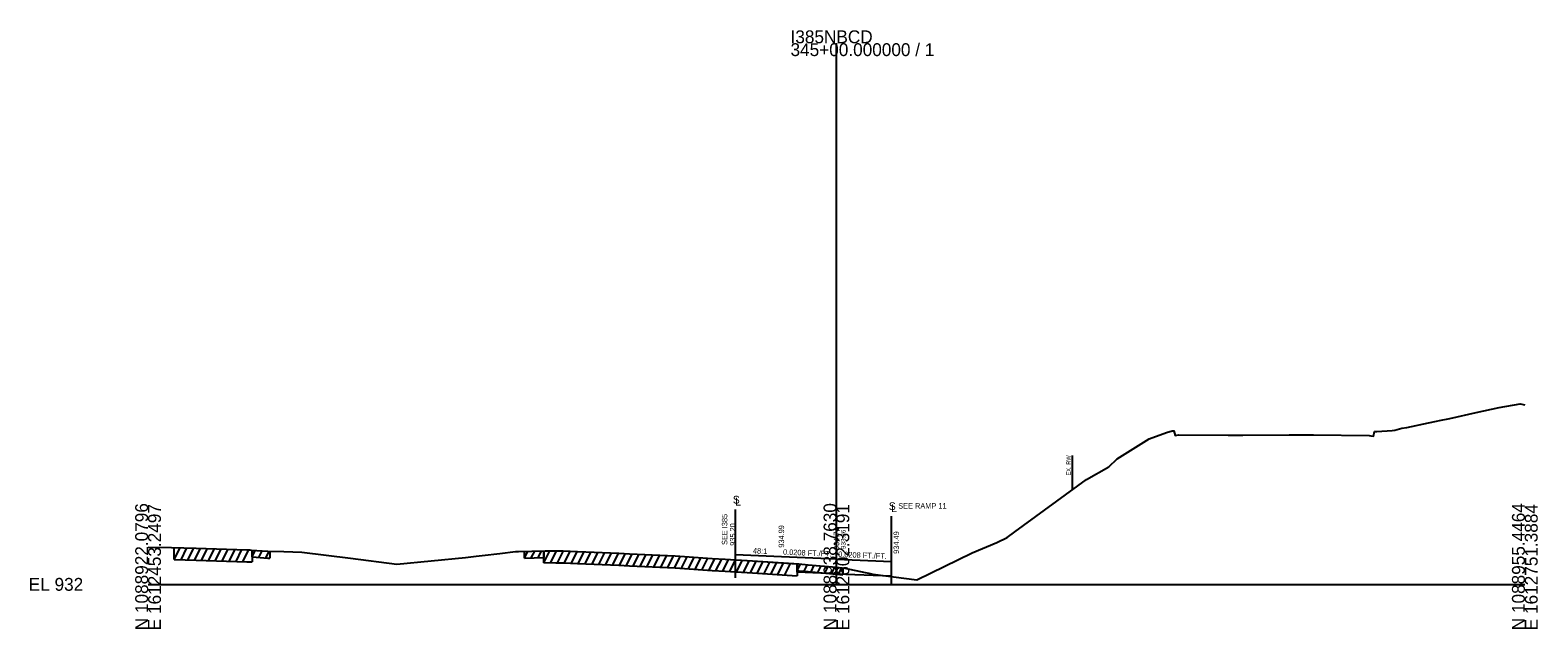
# Model space of a CAD drawing. Extents: x -26 to 1613369, y -10 to 1281970.
# Drawn here: x -25.7 to 302.8, y 15990.3 to 16120.7 of the extents above; entities that cross this region are included whole.
import ezdxf

# ---------------------------------------------------------------- set-up
doc = ezdxf.new("R2010")
doc.units = 0
for name, color, linetype in [('RD_EX_Misc', 7, 'Continuous'), ('RD_GPK_XS_Cell', 7, 'Continuous'), ('RD_Sketch1', 7, 'Continuous'), ('RD_XS_Base', 7, 'Continuous'), ('RD_XS_ExGround', 7, 'Continuous'), ('RD_XS_ExPaveRet', 7, 'Continuous'), ('RD_XS_ExRW', 7, 'Continuous'), ('RD_XS_MatchLine', 7, 'Continuous'), ('RD_XS_Pave', 7, 'Continuous'), ('RD_XS_PaveShd', 7, 'Continuous'), ('RD_XS_TX_Elev_EX', 7, 'Continuous'), ('RD_XS_TX_Elev_PR', 7, 'Continuous'), ('RD_XS_TX_MatchLine', 7, 'Continuous'), ('RD_XS_TX_Notes', 7, 'Continuous'), ('RD_XS_TX_ShdSlope', 7, 'Continuous'), ('RD_XS_TX_Slope', 7, 'Continuous')]:
    doc.layers.add(name, color=color, linetype=linetype)

msp = doc.modelspace()

# ---------------------------------------------------------------- linework, layer by layer
at = {"layer": 'RD_EX_Misc'}
for p, q in [((22.67, 16005.97), (22.67, 16007.47)), ((26.5, 16007.19), (26.5, 16005.69)), ((82, 16005.69), (82, 16007.19)), ((86.24, 16007.32), (86.24, 16005.82)), ((22.67, 16005.97), (26.08, 16005.7)), ((26.08, 16005.7), (26.5, 16005.69)), ((82, 16005.69), (86.24, 16005.82)), ((141.46, 16002.98), (141.46, 16004.48)), ((141.46, 16002.98), (141.83, 16002.96)), ((141.83, 16002.96), (143.83, 16002.78)), ((151.37, 16003.6), (151.37, 16002.1)), ((143.83, 16002.78), (150, 16002.22)), ((150, 16002.22), (151.37, 16002.1))]:
    msp.add_line(p, q, dxfattribs=at)
at = {"layer": 'RD_GPK_XS_Cell'}
for p, q in [((150, 16000), (150, 16117.87)), ((0, 16000), (150, 16000)), ((150, 16000), (300, 16000))]:
    msp.add_line(p, q, dxfattribs=at)
at = {"layer": 'RD_Sketch1'}
for p, q in [((22.67, 16005.97), (23.39, 16007.41)), ((24.17, 16005.85), (24.89, 16007.29)), ((25.67, 16005.73), (26.4, 16007.19)), ((82, 16005.69), (82.76, 16007.21)), ((83.5, 16005.74), (84.26, 16007.26)), ((85, 16005.78), (85.76, 16007.31)), ((141.46, 16002.98), (142.19, 16004.43)), ((142.96, 16002.86), (143.68, 16004.29)), ((144.46, 16002.72), (145.18, 16004.16)), ((145.96, 16002.59), (146.68, 16004.02)), ((147.46, 16002.45), (148.18, 16003.89)), ((148.96, 16002.32), (149.68, 16003.75)), ((150.46, 16002.18), (151.18, 16003.61))]:
    msp.add_line(p, q, dxfattribs=at)
at = {"layer": 'RD_XS_Base'}
for p, q in [((128, 16005.32), (131.74, 16005.09)), ((131.74, 16005.09), (138, 16004.7)), ((138, 16004.7), (141.46, 16004.48)), ((141.46, 16002.67), (141.46, 16004.48)), ((150, 16002.32), (141.46, 16002.67)), ((150, 16002.32), (162, 16001.82))]:
    msp.add_line(p, q, dxfattribs=at)
at = {"layer": 'RD_XS_ExGround'}
msp.add_lwpolyline([(0, 16008.13), (5.1, 16008.01), (10.49, 16007.9), (21.55, 16007.53), (22.14, 16007.51), (22.5, 16007.48), (26.08, 16007.2), (29.56, 16007.12), (33.53, 16006.98), (44.11, 16005.69), (54.2, 16004.41), (69.14, 16005.88), (71.52, 16006.11), (72.81, 16006.27), (76.65, 16006.72), (80.06, 16007.14), (80.69, 16007.15), (86.54, 16007.33), (88.89, 16007.32), (90.44, 16007.31), (93.61, 16007.16), (102.61, 16006.76), (104.9, 16006.65), (114.84, 16006.21), (122.93, 16005.65), (125.74, 16005.46), (131.74, 16005.09), (141.83, 16004.46), (143.83, 16004.28), (150, 16003.72), (151.84, 16003.55), (156.23, 16002.57), (157.05, 16002.41), (157.93, 16002.25), (167.52, 16000.96), (179.6, 16006.86), (184.92, 16009.11), (187.21, 16010.23), (188.88, 16011.47), (204.5, 16022.85), (209.35, 16025.61), (211.15, 16027.33), (218.18, 16031.69), (221.89, 16033.04), (223.14, 16033.43), (223.55, 16033.43), (223.8, 16032.44), (224.56, 16032.54), (235.39, 16032.52), (236.33, 16032.49), (238.59, 16032.5), (248.68, 16032.58), (253.96, 16032.55), (266.11, 16032.4), (266.48, 16032.36), (267.03, 16032.3), (267.28, 16033.3), (267.78, 16033.3), (271.12, 16033.54), (271.69, 16033.57), (272.66, 16033.86), (273.22, 16034), (274.3, 16034.13), (279.04, 16035.2), (280.73, 16035.57), (281.43, 16035.72), (283.67, 16036.13), (289.37, 16037.44), (294.44, 16038.52), (298.96, 16039.29), (300, 16039.12)], dxfattribs=at)
at = {"layer": 'RD_XS_ExPaveRet'}
for p, q in [((5.68, 16005.4), (5.68, 16008)), ((5.68, 16005.4), (6.97, 16007.98)), ((7.18, 16005.37), (8.47, 16007.94)), ((8.68, 16005.34), (9.97, 16007.91)), ((10.18, 16005.31), (11.46, 16007.87)), ((11.68, 16005.26), (12.96, 16007.82)), ((13.18, 16005.21), (14.46, 16007.77)), ((14.68, 16005.16), (15.96, 16007.72)), ((16.18, 16005.11), (17.46, 16007.66)), ((17.68, 16005.06), (18.96, 16007.61)), ((19.18, 16005.01), (20.46, 16007.56)), ((20.68, 16004.96), (21.96, 16007.51)), ((22.67, 16007.47), (22.67, 16004.87)), ((86.24, 16004.72), (87.54, 16007.33)), ((86.24, 16004.72), (86.24, 16007.32)), ((87.74, 16004.73), (89.03, 16007.32)), ((89.24, 16004.72), (90.53, 16007.3)), ((90.74, 16004.69), (92.01, 16007.23)), ((92.24, 16004.62), (93.51, 16007.16)), ((93.74, 16004.55), (95.01, 16007.1)), ((95.24, 16004.49), (96.51, 16007.03)), ((96.74, 16004.42), (98.01, 16006.96)), ((98.24, 16004.35), (99.51, 16006.9)), ((99.74, 16004.29), (101.01, 16006.83)), ((101.24, 16004.22), (102.51, 16006.76)), ((102.74, 16004.15), (104.01, 16006.69)), ((104.24, 16004.08), (105.51, 16006.62)), ((105.74, 16004.01), (107.01, 16006.56)), ((107.24, 16003.95), (108.51, 16006.49)), ((108.74, 16003.88), (110.01, 16006.42)), ((110.24, 16003.81), (111.51, 16006.36)), ((111.74, 16003.74), (113.01, 16006.29)), ((113.24, 16003.68), (114.51, 16006.22)), ((114.74, 16003.61), (116, 16006.13)), ((5.68, 16005.4), (10.49, 16005.3)), ((10.49, 16005.3), (21.55, 16004.93)), ((21.55, 16004.93), (22.14, 16004.91)), ((22.14, 16004.91), (22.5, 16004.88)), ((22.5, 16004.88), (22.67, 16004.87)), ((86.24, 16004.72), (86.54, 16004.73)), ((86.54, 16004.73), (88.89, 16004.72)), ((88.89, 16004.72), (90.44, 16004.71)), ((90.44, 16004.71), (93.61, 16004.56)), ((93.61, 16004.56), (102.61, 16004.16)), ((102.61, 16004.16), (104.9, 16004.05)), ((104.9, 16004.05), (114.84, 16003.61)), ((114.84, 16003.61), (122.93, 16003.05)), ((116.24, 16003.51), (117.5, 16006.02)), ((117.74, 16003.41), (119, 16005.92)), ((119.24, 16003.31), (120.5, 16005.82)), ((120.74, 16003.2), (122, 16005.72)), ((122.24, 16003.1), (123.5, 16005.61)), ((122.93, 16003.05), (125.74, 16002.86)), ((123.74, 16003), (125, 16005.51)), ((125.24, 16002.89), (126.5, 16005.41)), ((125.74, 16002.86), (131.74, 16002.49)), ((126.74, 16002.8), (128, 16005.32)), ((128.24, 16002.7), (129.5, 16005.23)), ((129.74, 16002.61), (131, 16005.13)), ((131.24, 16002.52), (132.5, 16005.04)), ((132.74, 16002.42), (134, 16004.95)), ((134.24, 16002.33), (135.5, 16004.85)), ((135.74, 16002.24), (137, 16004.76)), ((137.24, 16002.15), (138.5, 16004.67)), ((138.74, 16002.05), (140, 16004.57)), ((141.46, 16004.48), (141.46, 16001.88)), ((131.74, 16002.49), (141.46, 16001.88))]:
    msp.add_line(p, q, dxfattribs=at)
at = {"layer": 'RD_XS_ExRW'}
msp.add_line((201.38, 16028.09), (201.38, 16020.57), dxfattribs=at)
at = {"layer": 'RD_XS_MatchLine'}
for p, q in [((128, 16005.32), (128, 16006.4)), ((162, 16001.7), (162, 16004.98))]:
    msp.add_line(p, q, dxfattribs=at)
at = {"layer": 'RD_XS_Pave'}
for q in [(138, 16005.98), (162, 16004.98)]:
    msp.add_line((150, 16005.48), q, dxfattribs=at)
at = {"layer": 'RD_XS_PaveShd'}
msp.add_line((138, 16005.98), (128, 16006.4), dxfattribs=at)
at = {"layer": 'RD_XS_TX_MatchLine'}
for p, q in [((128, 16006.4), (128, 16016.29)), ((162, 16004.98), (162, 16014.87)), ((128, 16001.4), (128, 16006.4)), ((162, 15999.98), (162, 16004.98))]:
    msp.add_line(p, q, dxfattribs=at)

# ---------------------------------------------------------------- texts
at = {"layer": 'RD_GPK_XS_Cell'}
for s, p in [('345+00.000000 / 1', (140, 16115.07)), ('I385NBCD', (140, 16117.87)), ('EL 932', (-26, 15998.6))]:
    msp.add_text(s, height=2.8, dxfattribs=at).set_placement(p)
for s, p in [('N 1088922.0796', (0, 15990)), ('E 1612453.2497', (2.8, 15990)), ('N 1088938.7630', (150, 15990)), ('E 1612602.3191', (152.8, 15990)), ('N 1088955.4464', (300, 15990)), ('E 1612751.3884', (302.8, 15990))]:
    msp.add_text(s, height=2.8, rotation=90, dxfattribs=at).set_placement(p)
at = {"layer": 'RD_XS_ExRW'}
msp.add_text('EX. RW', height=0.9, rotation=90, dxfattribs=at).set_placement((201.02, 16023.69))
at = {"layer": 'RD_XS_TX_Elev_EX'}
msp.add_text('933.86', height=1, rotation=90, dxfattribs=at).set_placement((152, 16007.68))
at = {"layer": 'RD_XS_TX_Elev_PR'}
for s, p in [('935.20', (128, 16008.4)), ('934.99', (138.6, 16007.98)), ('934.74', (150.6, 16007.48)), ('934.49', (163.64, 16006.64))]:
    msp.add_text(s, height=1.2, rotation=90, dxfattribs=at).set_placement(p)
at = {"layer": 'RD_XS_TX_MatchLine'}
for s, p in [('S', (127.42, 16017.6)), ('L', (127.93, 16017.17)), ('S', (161.42, 16016.19)), ('L', (161.93, 16015.75))]:
    msp.add_text(s, height=1.68, dxfattribs=at).set_placement(p)
at = {"layer": 'RD_XS_TX_Notes'}
msp.add_text('SEE RAMP 11', height=1.2, dxfattribs=at).set_placement((163.47, 16016.49))
msp.add_text('SEE I385', height=1.2, rotation=90, dxfattribs=at).set_placement((126.23, 16008.57))
at = {"layer": 'RD_XS_TX_ShdSlope'}
msp.add_text('48:1', height=1.2, rotation=357.6141, dxfattribs=at).set_placement((131.79, 16006.74))
at = {"layer": 'RD_XS_TX_Slope'}
for p in [(138.35, 16006.47), (150.35, 16005.97)]:
    msp.add_text('0.0208 FT./FT.', height=1.2, rotation=357.6141, dxfattribs=at).set_placement(p)

doc.saveas('drawing.dxf')
